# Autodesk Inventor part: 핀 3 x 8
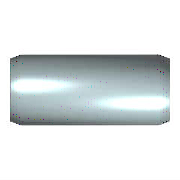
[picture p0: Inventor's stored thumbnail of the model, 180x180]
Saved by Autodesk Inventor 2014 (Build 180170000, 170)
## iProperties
IsCustomPart: 1
Created: 2012-02
Part Number: 핀 3 x 8
Material: 강철, 연강
Description: 평행 핀
Document SubType Name: Modeling
Standard: KS B 1320
Designer: mduedu
Standards Organization: KS
Language: ko-KR
Size Designation: B 3 x  8
Categories: <MemberInstance><Categories><Category DisplayName="조임쇠" InternalName="e4da775c-781d-43d5-af7c-5136215cf5a6" Mnemonic="FSTN"><Category DisplayName="핀" InternalNa
Density: 7.86 g/cm^3
Appearance: 노란색
Mass: 0.439658 g
Surface Area: 0.870195 cm^2
Volume: 0.0559361 cm^3
Author: mduedu
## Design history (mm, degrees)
sketch "스케치"
  geometry: C1 r 1.5 at (0, 0); 1 further point
  constraints: 1 centre point, 1 coincident
  dimensions: "d1" = 3 diameter of C1 (= NND)
extrude "본체" new body sketch "스케치" distance "d2" = 8 (= NLG); taper "d3" = 0 deg
chamfer "스케치2" distance "d8" = 0.5 (= PHH); stored, may be unused: angle "d9" = 15 deg (= FAWI), second distance "d12" = 0.5 (= PHH)
body "Solid1"
chamfer "모따기1" distance "d4" = 0.5 (= PHH); stored, may be unused: angle "d5" = 15 deg (= FAWI), second distance "d11" = 0.5 (= PHH)
other parameters: "NND" = 3 [user parameter; used in 1 equation term], "NLG" = 8 [user parameter; used in 1 equation term], "PHH" = 0.5 [user parameter; used in 4 equation terms], "FAWI" = 15 deg [user parameter; used in 2 equation terms], "d13" = 0, "d15" = 0, "d16" = 0, "KAH" = 0.4 [user parameter]
